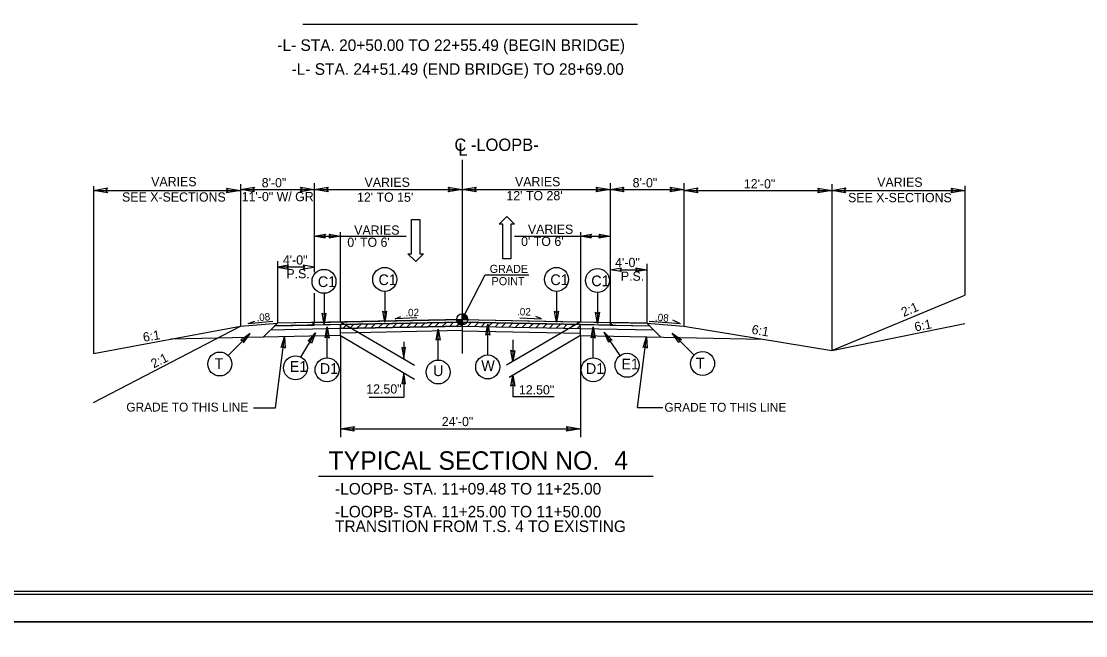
# Model space of a CAD drawing. Extents: x 981824 to 982276, y 44828 to 45204.
# Drawn here: x 982129 to 982198.1, y 45001.1 to 45041 of the extents above; entities that cross this region are included whole.
import ezdxf

# ---------------------------------------------------------------- set-up
doc = ezdxf.new("R2010")
doc.units = 0
for name, color, linetype in [('Default', 7, 'Continuous'), ('Old_Level_1', 7, 'Continuous'), ('Old_Level_11', 7, 'Continuous'), ('Old_Level_18', 7, 'Continuous'), ('Old_Level_2', 7, 'Continuous'), ('Old_Level_20', 7, 'Continuous'), ('Old_Level_21', 7, 'Continuous'), ('Old_Level_3', 7, 'Continuous'), ('Old_Level_50', 7, 'Continuous'), ('Old_Level_51', 7, 'Continuous'), ('Prop Dimension Text', 7, 'Continuous'), ('Prop Lane Arrow Through CELL', 7, 'Continuous'), ('Prop Roadway Profile Bench Mark Info Text', 7, 'Continuous'), ('Typical Terminator CELL', 7, 'Continuous')]:
    doc.layers.add(name, color=color, linetype=linetype)

msp = doc.modelspace()

# ---------------------------------------------------------------- linework, layer by layer
at = {"layer": 'Default'}
for points in [[(982154.647, 45021.71), (982153.247, 45021.661), (982153.613, 45021.799)], [(982161.339, 45021.71), (982162.74, 45021.661), (982162.374, 45021.799)]]:
    msp.add_lwpolyline(points, dxfattribs=at)
at = {"layer": 'Old_Level_1'}
for p, q in [((982157.588, 45031.975), (982157.588, 45019.407)), ((982133.649, 45030.266), (982133.649, 45019.403)), ((982143.188, 45030.394), (982143.188, 45021.181)), ((982143.188, 45030.054), (982147.988, 45030.054)), ((982147.988, 45030.454), (982147.988, 45024.689)), ((982147.988, 45030.054), (982157.588, 45030.054)), ((982157.588, 45030.054), (982167.188, 45030.054)), ((982167.188, 45030.454), (982167.188, 45021.249)), ((982167.188, 45030.054), (982171.988, 45030.054)), ((982171.988, 45030.454), (982171.988, 45021.181)), ((982181.584, 45030.391), (982181.584, 45019.585)), ((982190.234, 45030.295), (982190.234, 45023.183)), ((982133.649, 45029.994), (982143.188, 45029.994)), ((982171.984, 45029.991), (982181.584, 45029.991)), ((982181.584, 45029.991), (982190.234, 45029.991)), ((982147.988, 45027.024), (982149.669, 45027.024)), ((982149.669, 45027.28), (982149.669, 45021.455)), ((982149.669, 45027.024), (982153.961, 45027.024)), ((982160.975, 45027.024), (982165.261, 45027.024)), ((982165.261, 45027.28), (982165.261, 45021.459)), ((982165.261, 45027.024), (982167.188, 45027.024)), ((982145.588, 45025.403), (982145.588, 45021.421)), ((982169.588, 45025.231), (982169.588, 45021.373)), ((982147.298, 45025.013), (982145.588, 45025.013)), ((982167.877, 45024.841), (982169.588, 45024.841)), ((982157.588, 45021.613), (982159.078, 45024.507)), ((982147.988, 45023.316), (982147.988, 45021.421)), ((982181.584, 45019.585), (982190.234, 45023.183)), ((982157.588, 45021.613), (982157.588, 45021.973)), ((982133.649, 45016.223), (982143.188, 45021.181)), ((982133.649, 45019.403), (982143.188, 45021.181)), ((982143.188, 45021.181), (982145.588, 45021.373)), ((982143.701, 45021.358), (982145.299, 45021.5)), ((982143.701, 45021.358), (982144.124, 45021.5)), ((982145.588, 45021.373), (982144.671, 45020.461)), ((982149.682, 45021.283), (982145.411, 45021.198)), ((982157.588, 45021.613), (982145.588, 45021.373)), ((982157.593, 45021.181), (982149.676, 45021.022)), ((982149.682, 45021.455), (982154.488, 45018.634)), ((982149.682, 45021.283), (982157.588, 45021.441)), ((982149.682, 45021.283), (982157.588, 45021.441)), ((982149.682, 45020.562), (982149.682, 45021.283)), ((982149.833, 45021.025), (982150.097, 45021.29)), ((982150.295, 45021.035), (982150.56, 45021.3)), ((982150.756, 45021.044), (982151.021, 45021.309)), ((982151.218, 45021.053), (982151.483, 45021.318)), ((982151.68, 45021.063), (982151.945, 45021.327)), ((982152.142, 45021.072), (982152.407, 45021.337)), ((982152.604, 45021.081), (982152.868, 45021.346)), ((982153.066, 45021.09), (982153.33, 45021.355)), ((982153.528, 45021.1), (982153.792, 45021.365)), ((982153.989, 45021.109), (982154.254, 45021.373)), ((982154.451, 45021.118), (982154.716, 45021.383)), ((982154.913, 45021.128), (982155.177, 45021.393)), ((982155.375, 45021.137), (982155.64, 45021.401)), ((982155.836, 45021.146), (982156.101, 45021.411)), ((982156.298, 45021.156), (982156.563, 45021.42)), ((982156.76, 45021.165), (982157.025, 45021.429)), ((982157.222, 45021.174), (982157.487, 45021.438)), ((982157.228, 45021.613), (982157.588, 45021.613)), ((982157.579, 45021.181), (982165.261, 45021.026)), ((982157.58, 45021.258), (982157.76, 45021.438)), ((982157.587, 45021.253), (982157.588, 45021.613)), ((982157.588, 45021.613), (982157.587, 45021.253)), ((982157.588, 45021.613), (982169.588, 45021.373)), ((982157.948, 45021.613), (982157.588, 45021.613)), ((982157.588, 45021.441), (982169.763, 45021.197)), ((982157.948, 45021.173), (982158.204, 45021.429)), ((982158.392, 45021.165), (982158.647, 45021.42)), ((982158.835, 45021.155), (982159.091, 45021.411)), ((982159.279, 45021.146), (982159.535, 45021.402)), ((982159.722, 45021.137), (982159.978, 45021.393)), ((982160.166, 45021.129), (982160.422, 45021.385)), ((982165.261, 45021.459), (982160.456, 45018.638)), ((982160.61, 45021.12), (982160.865, 45021.376)), ((982161.053, 45021.111), (982161.309, 45021.367)), ((982161.497, 45021.102), (982161.752, 45021.357)), ((982161.94, 45021.093), (982162.196, 45021.349)), ((982162.384, 45021.084), (982162.64, 45021.34)), ((982162.828, 45021.075), (982163.084, 45021.331)), ((982163.272, 45021.066), (982163.528, 45021.322)), ((982163.715, 45021.057), (982163.971, 45021.313)), ((982164.159, 45021.049), (982164.415, 45021.305)), ((982164.603, 45021.04), (982164.858, 45021.296)), ((982165.046, 45021.031), (982165.261, 45021.245)), ((982165.261, 45020.567), (982165.261, 45021.287)), ((982165.261, 45021.026), (982165.261, 45021.287)), ((982169.588, 45021.373), (982171.988, 45021.181)), ((982169.588, 45021.373), (982170.498, 45020.462)), ((982171.775, 45021.317), (982169.736, 45021.48)), ((982171.775, 45021.317), (982171.264, 45021.572)), ((982171.988, 45021.181), (982181.584, 45019.585)), ((982181.584, 45019.585), (982190.234, 45021.352)), ((982149.685, 45020.562), (982138.678, 45020.34)), ((982149.682, 45021.022), (982145.139, 45020.927)), ((982145.461, 45015.878), (982146.055, 45020.489)), ((982157.599, 45020.884), (982149.682, 45020.725)), ((982149.682, 45020.562), (982149.682, 45013.962)), ((982149.685, 45020.562), (982154.491, 45017.742)), ((982157.573, 45020.883), (982165.261, 45020.729)), ((982165.261, 45020.567), (982160.629, 45017.849)), ((982165.261, 45021.026), (982170.029, 45020.931)), ((982165.261, 45020.567), (982177.109, 45020.329)), ((982165.261, 45020.567), (982165.261, 45013.962)), ((982168.97, 45015.883), (982169.563, 45020.481)), ((982153.791, 45020.161), (982153.791, 45019.078)), ((982160.875, 45020.285), (982160.875, 45018.885)), ((982153.791, 45018.153), (982153.791, 45016.563)), ((982160.875, 45017.993), (982160.875, 45016.593)), ((982151.546, 45016.563), (982153.791, 45016.563)), ((982163.564, 45016.593), (982160.875, 45016.593)), ((982144.043, 45015.878), (982145.461, 45015.878)), ((982168.97, 45015.883), (982170.61, 45015.883)), ((982149.682, 45014.509), (982165.261, 45014.509))]:
    msp.add_line(p, q, dxfattribs=at)
for points in [[(982157.591, 45021.973), (982157.591, 45021.973), (982157.591, 45021.613)], [(982157.598, 45021.973), (982157.598, 45021.613)], [(982157.605, 45021.972), (982157.605, 45021.613)], [(982157.612, 45021.972), (982157.612, 45021.613)], [(982157.62, 45021.971), (982157.62, 45021.613)], [(982157.627, 45021.97), (982157.627, 45021.613)], [(982157.634, 45021.969), (982157.634, 45021.613)], [(982157.641, 45021.969), (982157.641, 45021.613)], [(982157.648, 45021.968), (982157.648, 45021.613)], [(982157.656, 45021.966), (982157.656, 45021.613)], [(982157.663, 45021.965), (982157.663, 45021.613)], [(982157.67, 45021.963), (982157.67, 45021.613)], [(982157.677, 45021.961), (982157.677, 45021.613)], [(982157.684, 45021.959), (982157.684, 45021.613)], [(982157.692, 45021.957), (982157.692, 45021.613)], [(982157.699, 45021.955), (982157.699, 45021.613)], [(982157.706, 45021.953), (982157.706, 45021.613)], [(982157.713, 45021.95), (982157.713, 45021.613)], [(982157.72, 45021.947), (982157.72, 45021.613)], [(982157.728, 45021.944), (982157.728, 45021.613)], [(982157.735, 45021.941), (982157.735, 45021.613)], [(982157.742, 45021.937), (982157.742, 45021.613)], [(982157.749, 45021.934), (982157.749, 45021.613)], [(982157.756, 45021.93), (982157.756, 45021.613)], [(982157.764, 45021.926), (982157.764, 45021.613)], [(982157.771, 45021.922), (982157.771, 45021.613)], [(982157.778, 45021.918), (982157.778, 45021.613)], [(982157.785, 45021.913), (982157.785, 45021.613)], [(982157.792, 45021.909), (982157.792, 45021.613)], [(982157.8, 45021.903), (982157.8, 45021.613)], [(982157.807, 45021.898), (982157.807, 45021.613)], [(982157.814, 45021.893), (982157.814, 45021.613)], [(982157.821, 45021.886), (982157.821, 45021.613)], [(982157.828, 45021.88), (982157.828, 45021.613)], [(982157.836, 45021.873), (982157.836, 45021.613)], [(982157.843, 45021.866), (982157.843, 45021.613)], [(982157.85, 45021.859), (982157.85, 45021.613)], [(982157.857, 45021.851), (982157.857, 45021.613)], [(982157.864, 45021.842), (982157.864, 45021.613)], [(982157.872, 45021.833), (982157.872, 45021.613)], [(982157.879, 45021.824), (982157.879, 45021.613)], [(982157.886, 45021.813), (982157.886, 45021.613)], [(982157.893, 45021.802), (982157.893, 45021.613)], [(982157.9, 45021.79), (982157.9, 45021.613)], [(982157.908, 45021.777), (982157.908, 45021.613)], [(982157.915, 45021.762), (982157.915, 45021.613)], [(982157.229, 45021.613), (982157.229, 45021.573)], [(982157.236, 45021.613), (982157.236, 45021.531)], [(982157.244, 45021.613), (982157.244, 45021.505)], [(982157.251, 45021.613), (982157.251, 45021.484)], [(982157.258, 45021.613), (982157.258, 45021.467)], [(982157.265, 45021.613), (982157.265, 45021.452)], [(982157.272, 45021.613), (982157.272, 45021.438)], [(982157.28, 45021.613), (982157.28, 45021.425)], [(982157.287, 45021.613), (982157.287, 45021.414)], [(982157.294, 45021.613), (982157.294, 45021.404)], [(982157.301, 45021.613), (982157.301, 45021.394)], [(982157.308, 45021.613), (982157.308, 45021.385)], [(982157.316, 45021.613), (982157.316, 45021.377)], [(982157.323, 45021.613), (982157.323, 45021.369)], [(982157.33, 45021.613), (982157.33, 45021.361)], [(982157.337, 45021.613), (982157.337, 45021.353)], [(982157.344, 45021.613), (982157.344, 45021.347)], [(982157.352, 45021.613), (982157.352, 45021.341)], [(982157.359, 45021.613), (982157.359, 45021.334)], [(982157.366, 45021.613), (982157.366, 45021.329)], [(982157.373, 45021.613), (982157.373, 45021.323)], [(982157.38, 45021.613), (982157.38, 45021.318)], [(982157.388, 45021.613), (982157.388, 45021.313)], [(982157.395, 45021.613), (982157.395, 45021.309)], [(982157.402, 45021.613), (982157.402, 45021.304)], [(982157.409, 45021.613), (982157.409, 45021.3)], [(982157.416, 45021.613), (982157.416, 45021.296)], [(982157.424, 45021.613), (982157.424, 45021.292)], [(982157.431, 45021.613), (982157.431, 45021.289)], [(982157.438, 45021.613), (982157.438, 45021.285)], [(982157.445, 45021.613), (982157.445, 45021.282)], [(982157.452, 45021.613), (982157.452, 45021.279)], [(982157.46, 45021.613), (982157.46, 45021.276)], [(982157.467, 45021.613), (982157.467, 45021.273)], [(982157.474, 45021.613), (982157.474, 45021.271)], [(982157.481, 45021.613), (982157.481, 45021.269)], [(982157.488, 45021.613), (982157.488, 45021.267)], [(982157.496, 45021.613), (982157.496, 45021.265)], [(982157.503, 45021.613), (982157.503, 45021.263)], [(982157.51, 45021.613), (982157.51, 45021.261)], [(982157.517, 45021.613), (982157.517, 45021.26)], [(982157.524, 45021.613), (982157.524, 45021.258)], [(982157.532, 45021.613), (982157.532, 45021.257)], [(982157.539, 45021.613), (982157.539, 45021.256)], [(982157.546, 45021.613), (982157.546, 45021.255)], [(982157.553, 45021.613), (982157.553, 45021.254)], [(982157.56, 45021.613), (982157.56, 45021.253)], [(982157.568, 45021.613), (982157.568, 45021.253)], [(982157.575, 45021.613), (982157.575, 45021.253)], [(982157.582, 45021.613), (982157.582, 45021.253), (982157.582, 45021.253)], [(982157.922, 45021.745), (982157.922, 45021.613)], [(982157.929, 45021.725), (982157.929, 45021.613)], [(982157.936, 45021.701), (982157.936, 45021.613)], [(982157.944, 45021.664), (982157.944, 45021.613)]]:
    msp.add_lwpolyline(points, dxfattribs=at)
for points in [[(982149.682, 45021.022), (982157.593, 45021.181), (982157.588, 45021.441), (982149.682, 45021.283)], [(982157.579, 45021.181), (982165.261, 45021.026), (982165.261, 45021.287), (982157.584, 45021.441)]]:
    msp.add_lwpolyline(points, close=True, dxfattribs=at)
msp.add_circle((982157.587, 45021.613), 0.36, dxfattribs=at)
for start, end in [(359.99048, 89.99048), (179.99048, 269.99048)]:
    msp.add_arc((982157.587, 45021.613), 0.36, start, end, dxfattribs=at)
at = {"layer": 'Old_Level_11'}
for points in [[(982148.741, 45022.02), (982148.617, 45021.3), (982148.489, 45022.024), (982148.617, 45021.932)], [(982152.682, 45022.147), (982152.558, 45021.427), (982152.43, 45022.151), (982152.558, 45022.059)], [(982163.84, 45022.147), (982163.716, 45021.427), (982163.588, 45022.151), (982163.716, 45022.059)], [(982166.498, 45022.075), (982166.374, 45021.355), (982166.246, 45022.079), (982166.374, 45021.987)], [(982148.691, 45020.409), (982148.815, 45021.129), (982148.943, 45020.405), (982148.815, 45020.497)], [(982159.123, 45020.595), (982159.247, 45021.315), (982159.375, 45020.591), (982159.247, 45020.683)], [(982165.967, 45020.409), (982166.091, 45021.129), (982166.219, 45020.405), (982166.091, 45020.497)], [(982147.592, 45020.195), (982148.075, 45020.743), (982147.804, 45020.059), (982147.744, 45020.205)], [(982155.907, 45020.266), (982156.031, 45020.986), (982156.159, 45020.262), (982156.031, 45020.354)], [(982167.108, 45020.116), (982166.799, 45020.778), (982167.317, 45020.257), (982167.159, 45020.259)]]:
    msp.add_lwpolyline(points, close=True, dxfattribs=at)
at = {"layer": 'Old_Level_18'}
msp.add_lwpolyline([(982227.72, 45087.969), (982107.72, 45087.969), (982107.72, 45003.969), (982227.72, 45003.969)], close=True, dxfattribs=at)
at = {"layer": 'Old_Level_21'}
for p, q in [((982145.588, 45021.373), (982145.411, 45021.198)), ((982147.988, 45021.421), (982145.588, 45021.373)), ((982147.988, 45021.421), (982147.811, 45021.246)), ((982147.811, 45021.246), (982147.988, 45021.421)), ((982147.811, 45021.246), (982147.988, 45021.249)), ((982147.988, 45021.249), (982147.988, 45021.421)), ((982167.363, 45021.245), (982167.188, 45021.421)), ((982167.188, 45021.421), (982167.188, 45021.249)), ((982169.588, 45021.373), (982167.188, 45021.421)), ((982167.188, 45021.421), (982167.363, 45021.245)), ((982167.188, 45021.249), (982167.363, 45021.245)), ((982167.363, 45021.245), (982169.763, 45021.197)), ((982169.763, 45021.197), (982169.588, 45021.373))]:
    msp.add_line(p, q, dxfattribs=at)
msp.add_lwpolyline([(982145.411, 45021.198), (982147.811, 45021.246), (982147.811, 45021.246)], dxfattribs=at)
for points in [[(982157.588, 45021.441), (982147.988, 45021.249), (982147.988, 45021.421), (982157.588, 45021.613)], [(982157.588, 45021.613), (982167.188, 45021.421), (982167.188, 45021.249), (982157.584, 45021.44)]]:
    msp.add_lwpolyline(points, close=True, dxfattribs=at)
at = {"layer": 'Old_Level_3'}
msp.add_line((982159.078, 45024.507), (982161.924, 45024.507), dxfattribs=at)
at = {"layer": 'Old_Level_50'}
msp.add_lwpolyline([(982228.72, 45088.173), (982095.4, 45088.173), (982095.4, 45003.765), (982228.72, 45003.765)], close=True, dxfattribs=at)
at = {"layer": 'Old_Level_51'}
for points in [[(982229.08, 45089.969), (982094.36, 45089.969), (982094.36, 45001.969), (982229.08, 45001.969)], [(982229.08, 45001.969), (982094.36, 45001.969), (982094.36, 44913.969), (982229.08, 44913.969)]]:
    msp.add_lwpolyline(points, close=True, dxfattribs=at)
at = {"layer": 'Prop Dimension Text'}
for p, q in [((982148.617, 45023.31), (982148.617, 45021.3)), ((982152.558, 45023.437), (982152.558, 45021.427)), ((982163.716, 45023.437), (982163.716, 45021.427)), ((982166.374, 45023.364), (982166.374, 45021.355)), ((982148.815, 45019.119), (982148.815, 45021.129)), ((982159.247, 45019.305), (982159.247, 45021.315)), ((982166.091, 45019.119), (982166.091, 45021.129)), ((982142.396, 45019.268), (982143.818, 45020.689)), ((982147.108, 45019.173), (982148.075, 45020.743)), ((982156.031, 45018.976), (982156.031, 45020.986)), ((982167.847, 45019.269), (982166.799, 45020.778)), ((982172.651, 45019.295), (982171.23, 45020.716))]:
    msp.add_line(p, q, dxfattribs=at)
for centre in [(982148.617, 45024.087), (982152.558, 45024.214), (982163.716, 45024.214), (982166.374, 45024.142), (982141.847, 45018.719), (982146.767, 45018.474), (982148.814, 45018.341), (982159.246, 45018.527), (982166.09, 45018.341), (982168.295, 45018.634), (982173.201, 45018.746), (982156.03, 45018.198)]:
    msp.add_circle(centre, 0.778, dxfattribs=at)
at = {"layer": 'Prop Lane Arrow Through CELL'}
for p, q in [((982154.304, 45025.873), (982154.304, 45028.113)), ((982154.304, 45028.113), (982154.832, 45028.113)), ((982154.832, 45028.113), (982154.832, 45025.873)), ((982159.986, 45027.796), (982160.482, 45028.3)), ((982160.482, 45028.3), (982160.994, 45027.796)), ((982160.226, 45027.796), (982159.986, 45027.796)), ((982160.226, 45025.556), (982160.226, 45027.796)), ((982160.994, 45027.796), (982160.754, 45027.796)), ((982160.754, 45027.796), (982160.754, 45025.556)), ((982154.576, 45025.37), (982154.064, 45025.873)), ((982154.064, 45025.873), (982154.304, 45025.873)), ((982155.072, 45025.873), (982154.576, 45025.37)), ((982154.832, 45025.873), (982155.072, 45025.873)), ((982160.754, 45025.556), (982160.226, 45025.556))]:
    msp.add_line(p, q, dxfattribs=at)
at = {"layer": 'Prop Roadway Profile Bench Mark Info Text'}
for p, q in [((982147.246, 45040.785), (982168.966, 45040.785)), ((982148.267, 45011.444), (982169.987, 45011.444))]:
    msp.add_line(p, q, dxfattribs=at)
at = {"layer": 'Typical Terminator CELL'}
for points in [[(982134.549, 45029.839), (982133.649, 45029.994), (982134.554, 45030.154), (982134.439, 45029.994)], [(982142.288, 45030.149), (982143.188, 45029.994), (982142.283, 45029.834), (982142.398, 45029.994)], [(982144.088, 45029.899), (982143.188, 45030.054), (982144.093, 45030.214), (982143.978, 45030.054)], [(982147.088, 45030.209), (982147.988, 45030.054), (982147.083, 45029.894), (982147.198, 45030.054)], [(982148.888, 45029.899), (982147.988, 45030.054), (982148.893, 45030.214), (982148.778, 45030.054)], [(982156.688, 45030.209), (982157.588, 45030.054), (982156.683, 45029.894), (982156.798, 45030.054)], [(982158.488, 45029.899), (982157.588, 45030.054), (982158.493, 45030.214), (982158.378, 45030.054)], [(982166.288, 45030.209), (982167.188, 45030.054), (982166.283, 45029.894), (982166.398, 45030.054)], [(982168.088, 45029.899), (982167.188, 45030.054), (982168.093, 45030.214), (982167.978, 45030.054)], [(982171.088, 45030.209), (982171.988, 45030.054), (982171.083, 45029.894), (982171.198, 45030.054)], [(982172.884, 45029.836), (982171.984, 45029.991), (982172.889, 45030.151), (982172.774, 45029.991)], [(982180.684, 45030.146), (982181.584, 45029.991), (982180.679, 45029.831), (982180.794, 45029.991)], [(982182.484, 45029.836), (982181.584, 45029.991), (982182.489, 45030.151), (982182.374, 45029.991)], [(982189.334, 45030.146), (982190.234, 45029.991), (982189.329, 45029.831), (982189.444, 45029.991)], [(982148.699, 45026.901), (982147.988, 45027.024), (982148.703, 45027.15), (982148.612, 45027.024)], [(982148.958, 45027.146), (982149.669, 45027.024), (982148.954, 45026.897), (982149.045, 45027.024)], [(982165.973, 45026.901), (982165.261, 45027.024), (982165.976, 45027.15), (982165.886, 45027.024)], [(982166.476, 45027.146), (982167.188, 45027.024), (982166.472, 45026.897), (982166.563, 45027.024)], [(982146.308, 45025.137), (982145.588, 45025.013), (982146.312, 45024.885), (982146.22, 45025.013)], [(982147.268, 45024.889), (982147.988, 45025.013), (982147.264, 45025.141), (982147.356, 45025.013)], [(982167.908, 45024.717), (982167.188, 45024.841), (982167.912, 45024.969), (982167.82, 45024.841)], [(982168.868, 45024.965), (982169.588, 45024.841), (982168.864, 45024.713), (982168.956, 45024.841)], [(982143.396, 45020.092), (982143.818, 45020.689), (982143.215, 45020.268), (982143.371, 45020.242)], [(982145.843, 45019.79), (982146.055, 45020.489), (982146.092, 45019.755), (982145.977, 45019.862)], [(982169.35, 45019.782), (982169.563, 45020.481), (982169.6, 45019.746), (982169.484, 45019.854)], [(982171.651, 45020.119), (982171.23, 45020.716), (982171.832, 45020.295), (982171.677, 45020.269)], [(982153.667, 45019.798), (982153.791, 45019.078), (982153.919, 45019.802), (982153.791, 45019.71)], [(982160.999, 45019.605), (982160.875, 45018.885), (982160.747, 45019.609), (982160.875, 45019.517)], [(982153.915, 45017.433), (982153.791, 45018.153), (982153.663, 45017.429), (982153.791, 45017.521)], [(982160.751, 45017.273), (982160.875, 45017.993), (982161.003, 45017.269), (982160.875, 45017.361)], [(982150.582, 45014.354), (982149.682, 45014.509), (982150.587, 45014.669), (982150.472, 45014.509)], [(982164.361, 45014.664), (982165.261, 45014.509), (982164.356, 45014.349), (982164.471, 45014.509)]]:
    msp.add_lwpolyline(points, close=True, dxfattribs=at)

# ---------------------------------------------------------------- texts
at = {"layer": 'Old_Level_1'}
for s, height, p in [('C -LOOPB-', 0.8, (982157.085, 45032.559)), ('L', 0.8, (982157.344, 45032.242)), ('VARIES', 0.6, (982137.396, 45030.266)), ('8\'-0"', 0.6, (982144.572, 45030.193)), ('VARIES', 0.6, (982151.248, 45030.225)), ('VARIES', 0.6, (982161.018, 45030.265)), ('8\'-0"', 0.6, (982168.657, 45030.193)), ('12\'-0"', 0.6, (982175.876, 45030.121)), ('SEE X-SECTIONS', 0.6, (982135.503, 45029.266)), ('11\'-0" W/ GR', 0.6, (982143.273, 45029.293)), ("12' TO 15'", 0.6, (982150.761, 45029.254)), ("12' TO 28'", 0.6, (982160.459, 45029.355)), ('VARIES', 0.6, (982150.576, 45027.116)), ('VARIES', 0.6, (982161.859, 45027.171)), ("0' TO 6'", 0.6, (982150.13, 45026.329)), ("0' TO 6'", 0.6, (982161.414, 45026.385)), ('4\'-0"', 0.6, (982145.947, 45025.177)), ('4\'-0"', 0.6, (982167.523, 45025.014)), ('P.S.', 0.6, (982146.175, 45024.284)), ('P.S.', 0.6, (982167.889, 45024.126)), ('12.50"', 0.6, (982151.363, 45016.799)), ('12.50"', 0.6, (982161.273, 45016.743)), ('24\'-0"', 0.6, (982156.265, 45014.683))]:
    msp.add_text(s, height=height, dxfattribs=at).set_placement(p)
for s, rotation, p in [('2:1', 22.58277, (982186.248, 45021.772)), ('6:1', 350.56093, (982176.352, 45020.683)), ('6:1', 11.53964, (982187.02, 45020.823)), ('6:1', 9.46174, (982136.912, 45020.152)), ('2:1', 26.56457, (982137.561, 45018.427))]:
    msp.add_text(s, height=0.6, rotation=rotation, dxfattribs=at).set_placement(p)
at = {"layer": 'Old_Level_2'}
for s, rotation, p in [('.08', 4.57392, (982144.25, 45021.489)), ('.02  ', 1.14402, (982153.901, 45021.812)), ('.02  ', 358.85598, (982161.147, 45021.882)), ('.08', 355.42608, (982170.092, 45021.528))]:
    msp.add_text(s, height=0.48, rotation=rotation, dxfattribs=at).set_placement(p)
at = {"layer": 'Old_Level_20'}
for s, p in [('C1', (982152.156, 45023.844)), ('C1', (982163.314, 45023.844)), ('C1', (982148.215, 45023.717)), ('C1', (982165.972, 45023.771)), ('T ', (982141.517, 45018.4)), ('E1', (982167.923, 45018.369)), ('T ', (982172.759, 45018.426)), ('E1', (982146.395, 45018.21)), ('D1', (982148.347, 45018.077)), ('U', (982155.7, 45017.934)), ('W', (982158.827, 45018.263)), ('D1', (982165.623, 45018.077))]:
    msp.add_text(s, height=0.696, dxfattribs=at).set_placement(p)
at = {"layer": 'Old_Level_3'}
for s, height, p in [('GRADE TO THIS LINE', 0.576, (982135.782, 45015.632)), ('TYPICAL SECTION NO.  ', 1.2, (982148.915, 45011.847)), ('4', 1.2, (982167.467, 45011.863))]:
    msp.add_text(s, height=height, dxfattribs=at).set_placement(p)
at = {"layer": 'Prop Dimension Text'}
for s, height, p in [(' -L- STA. 20+50.00 TO 22+55.49 (BEGIN BRIDGE)', 0.75, (982145.307, 45039.052)), ('-L- STA. 24+51.49 (END BRIDGE) TO 28+69.00', 0.75, (982146.511, 45037.5)), ('VARIES', 0.6, (982184.538, 45030.228)), ('SEE X-SECTIONS', 0.6, (982182.645, 45029.228)), ('GRADE', 0.5248, (982159.371, 45024.634)), ('POINT', 0.5248, (982159.497, 45023.838)), ('GRADE TO THIS LINE', 0.576, (982170.719, 45015.618)), (' -LOOPB- STA. 11+09.48 TO 11+25.00', 0.75, (982149.054, 45010.241)), (' -LOOPB- STA. 11+25.00 TO 11+50.00', 0.75, (982149.054, 45008.755)), (' TRANSITION FROM T.S. 4 TO EXISTING', 0.75, (982149.054, 45007.805))]:
    msp.add_text(s, height=height, dxfattribs=at).set_placement(p)

doc.saveas('drawing.dxf')
